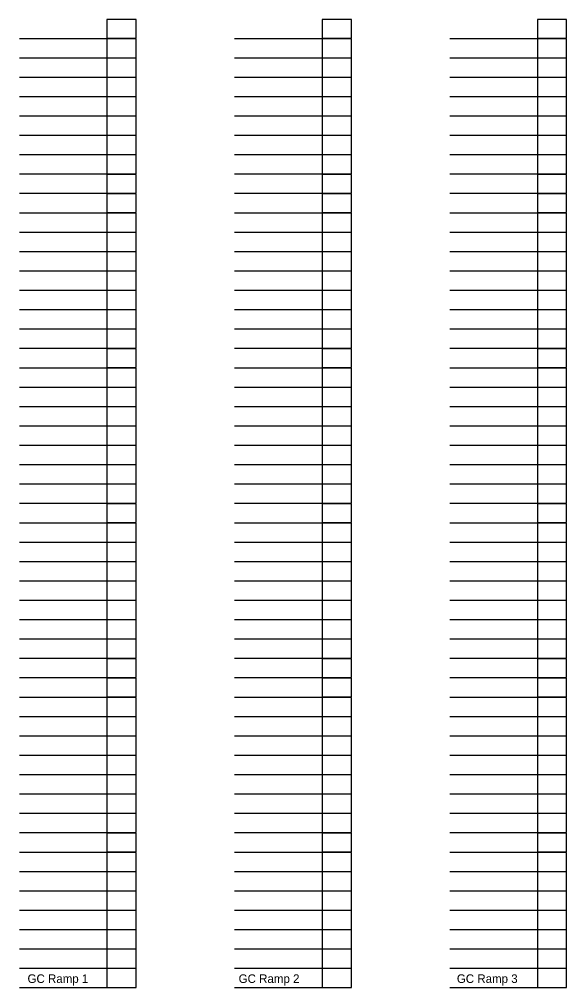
# Model space of a CAD drawing. Extents: x 625451 to 4181825, y 337941 to 441164.
# Drawn here: x 689151 to 701862, y 373673 to 396164 of the extents above; entities that cross this region are included whole.
import ezdxf

# ---------------------------------------------------------------- set-up
doc = ezdxf.new("R2010")
doc.units = 0
for name, color, linetype in [('PLOT_BDR-NOTUSED', 7, 'Continuous'), ('R_CX_Layout-GCRamp1', 7, 'Continuous'), ('R_CX_Layout-GCRamp2', 7, 'Continuous'), ('R_CX_Layout-GCRamp3', 7, 'Continuous'), ('R_No Plot_SEG2_FR', 7, 'Continuous')]:
    doc.layers.add(name, color=color, linetype=linetype)

msp = doc.modelspace()

# ---------------------------------------------------------------- linework, layer by layer
at = {"layer": 'PLOT_BDR-NOTUSED'}
for points in [[(691863, 396164), (691183, 396164), (691183, 395724), (691863, 395724)], [(696863, 396164), (696183, 396164), (696183, 395724), (696863, 395724)], [(701862, 396164), (701182, 396164), (701182, 395724), (701862, 395724)], [(691863, 395714), (691183, 395714), (691183, 395274), (691863, 395274)], [(696863, 395714), (696183, 395714), (696183, 395274), (696863, 395274)], [(701862, 395714), (701182, 395714), (701182, 395274), (701862, 395274)], [(691863, 395264), (691183, 395264), (691183, 394824), (691863, 394824)], [(696863, 395264), (696183, 395264), (696183, 394824), (696863, 394824)], [(701862, 395264), (701182, 395264), (701182, 394824), (701862, 394824)], [(691863, 394814), (691183, 394814), (691183, 394374), (691863, 394374)], [(696863, 394814), (696183, 394814), (696183, 394374), (696863, 394374)], [(701862, 394814), (701182, 394814), (701182, 394374), (701862, 394374)], [(691863, 394364), (691183, 394364), (691183, 393924), (691863, 393924)], [(696863, 394364), (696183, 394364), (696183, 393924), (696863, 393924)], [(701862, 394364), (701182, 394364), (701182, 393924), (701862, 393924)], [(691863, 393914), (691183, 393914), (691183, 393474), (691863, 393474)], [(696863, 393914), (696183, 393914), (696183, 393474), (696863, 393474)], [(701862, 393914), (701182, 393914), (701182, 393474), (701862, 393474)], [(691863, 393464), (691183, 393464), (691183, 393024), (691863, 393024)], [(696863, 393464), (696183, 393464), (696183, 393024), (696863, 393024)], [(701862, 393464), (701182, 393464), (701182, 393024), (701862, 393024)], [(691863, 393014), (691183, 393014), (691183, 392574), (691863, 392574)], [(696863, 393014), (696183, 393014), (696183, 392574), (696863, 392574)], [(701862, 393014), (701182, 393014), (701182, 392574), (701862, 392574)], [(691863, 392564), (691183, 392564), (691183, 392124), (691863, 392124)], [(696863, 392564), (696183, 392564), (696183, 392124), (696863, 392124)], [(701862, 392564), (701182, 392564), (701182, 392124), (701862, 392124)], [(691863, 392114), (691183, 392114), (691183, 391674), (691863, 391674)], [(696863, 392114), (696183, 392114), (696183, 391674), (696863, 391674)], [(701862, 392114), (701182, 392114), (701182, 391674), (701862, 391674)], [(691863, 391664), (691183, 391664), (691183, 391224), (691863, 391224)], [(696863, 391664), (696183, 391664), (696183, 391224), (696863, 391224)], [(701862, 391664), (701182, 391664), (701182, 391224), (701862, 391224)], [(691863, 391214), (691183, 391214), (691183, 390774), (691863, 390774)], [(696863, 391214), (696183, 391214), (696183, 390774), (696863, 390774)], [(701862, 391214), (701182, 391214), (701182, 390774), (701862, 390774)], [(691863, 390764), (691183, 390764), (691183, 390324), (691863, 390324)], [(696863, 390764), (696183, 390764), (696183, 390324), (696863, 390324)], [(701862, 390764), (701182, 390764), (701182, 390324), (701862, 390324)], [(691863, 390314), (691183, 390314), (691183, 389874), (691863, 389874)], [(696863, 390314), (696183, 390314), (696183, 389874), (696863, 389874)], [(701862, 390314), (701182, 390314), (701182, 389874), (701862, 389874)], [(691863, 389864), (691183, 389864), (691183, 389424), (691863, 389424)], [(696863, 389864), (696183, 389864), (696183, 389424), (696863, 389424)], [(701862, 389864), (701182, 389864), (701182, 389424), (701862, 389424)], [(691863, 389414), (691183, 389414), (691183, 388974), (691863, 388974)], [(696863, 389414), (696183, 389414), (696183, 388974), (696863, 388974)], [(701862, 389414), (701182, 389414), (701182, 388974), (701862, 388974)], [(691863, 388964), (691183, 388964), (691183, 388524), (691863, 388524)], [(696863, 388964), (696183, 388964), (696183, 388524), (696863, 388524)], [(701862, 388964), (701182, 388964), (701182, 388524), (701862, 388524)], [(691863, 388514), (691183, 388514), (691183, 388074), (691863, 388074)], [(696863, 388514), (696183, 388514), (696183, 388074), (696863, 388074)], [(701862, 388514), (701182, 388514), (701182, 388074), (701862, 388074)], [(691863, 388064), (691183, 388064), (691183, 387624), (691863, 387624)], [(696863, 388064), (696183, 388064), (696183, 387624), (696863, 387624)], [(701862, 388064), (701182, 388064), (701182, 387624), (701862, 387624)], [(691863, 387614), (691183, 387614), (691183, 387174), (691863, 387174)], [(696863, 387614), (696183, 387614), (696183, 387174), (696863, 387174)], [(701862, 387614), (701182, 387614), (701182, 387174), (701862, 387174)], [(691863, 387164), (691183, 387164), (691183, 386724), (691863, 386724)], [(696863, 387164), (696183, 387164), (696183, 386724), (696863, 386724)], [(701862, 387164), (701182, 387164), (701182, 386724), (701862, 386724)], [(691863, 386714), (691183, 386714), (691183, 386274), (691863, 386274)], [(696863, 386714), (696183, 386714), (696183, 386274), (696863, 386274)], [(701862, 386714), (701182, 386714), (701182, 386274), (701862, 386274)], [(691863, 386264), (691183, 386264), (691183, 385824), (691863, 385824)], [(696863, 386264), (696183, 386264), (696183, 385824), (696863, 385824)], [(701862, 386264), (701182, 386264), (701182, 385824), (701862, 385824)], [(691863, 385814), (691183, 385814), (691183, 385374), (691863, 385374)], [(696863, 385814), (696183, 385814), (696183, 385374), (696863, 385374)], [(701862, 385814), (701182, 385814), (701182, 385374), (701862, 385374)], [(691863, 385364), (691183, 385364), (691183, 384924), (691863, 384924)], [(696863, 385364), (696183, 385364), (696183, 384924), (696863, 384924)], [(701862, 385364), (701182, 385364), (701182, 384924), (701862, 384924)], [(691863, 384914), (691183, 384914), (691183, 384474), (691863, 384474)], [(696863, 384914), (696183, 384914), (696183, 384474), (696863, 384474)], [(701862, 384914), (701182, 384914), (701182, 384474), (701862, 384474)], [(691863, 384464), (691183, 384464), (691183, 384024), (691863, 384024)], [(696863, 384464), (696183, 384464), (696183, 384024), (696863, 384024)], [(701862, 384464), (701182, 384464), (701182, 384024), (701862, 384024)], [(691863, 384014), (691183, 384014), (691183, 383574), (691863, 383574)], [(696863, 384014), (696183, 384014), (696183, 383574), (696863, 383574)], [(701862, 384014), (701182, 384014), (701182, 383574), (701862, 383574)], [(691863, 383564), (691183, 383564), (691183, 383124), (691863, 383124)], [(696863, 383564), (696183, 383564), (696183, 383124), (696863, 383124)], [(701862, 383564), (701182, 383564), (701182, 383124), (701862, 383124)], [(691863, 383114), (691183, 383114), (691183, 382674), (691863, 382674)], [(696863, 383114), (696183, 383114), (696183, 382674), (696863, 382674)], [(701862, 383114), (701182, 383114), (701182, 382674), (701862, 382674)], [(691863, 382664), (691183, 382664), (691183, 382224), (691863, 382224)], [(696863, 382664), (696183, 382664), (696183, 382224), (696863, 382224)], [(701862, 382664), (701182, 382664), (701182, 382224), (701862, 382224)], [(691863, 382214), (691183, 382214), (691183, 381774), (691863, 381774)], [(696863, 382214), (696183, 382214), (696183, 381774), (696863, 381774)], [(701862, 382214), (701182, 382214), (701182, 381774), (701862, 381774)], [(691863, 381764), (691183, 381764), (691183, 381324), (691863, 381324)], [(696863, 381764), (696183, 381764), (696183, 381324), (696863, 381324)], [(701862, 381764), (701182, 381764), (701182, 381324), (701862, 381324)], [(691863, 381314), (691183, 381314), (691183, 380874), (691863, 380874)], [(696863, 381314), (696183, 381314), (696183, 380874), (696863, 380874)], [(701862, 381314), (701182, 381314), (701182, 380874), (701862, 380874)], [(691863, 380864), (691183, 380864), (691183, 380424), (691863, 380424)], [(696863, 380864), (696183, 380864), (696183, 380424), (696863, 380424)], [(701862, 380864), (701182, 380864), (701182, 380424), (701862, 380424)], [(691863, 380414), (691183, 380414), (691183, 379974), (691863, 379974)], [(696863, 380414), (696183, 380414), (696183, 379974), (696863, 379974)], [(701862, 380414), (701182, 380414), (701182, 379974), (701862, 379974)], [(691863, 379964), (691183, 379964), (691183, 379524), (691863, 379524)], [(696863, 379964), (696183, 379964), (696183, 379524), (696863, 379524)], [(701862, 379964), (701182, 379964), (701182, 379524), (701862, 379524)], [(691863, 379514), (691183, 379514), (691183, 379074), (691863, 379074)], [(696863, 379514), (696183, 379514), (696183, 379074), (696863, 379074)], [(701862, 379514), (701182, 379514), (701182, 379074), (701862, 379074)], [(691863, 379064), (691183, 379064), (691183, 378624), (691863, 378624)], [(696863, 379064), (696183, 379064), (696183, 378624), (696863, 378624)], [(701862, 379064), (701182, 379064), (701182, 378624), (701862, 378624)], [(691863, 378614), (691183, 378614), (691183, 378174), (691863, 378174)], [(696863, 378614), (696183, 378614), (696183, 378174), (696863, 378174)], [(701862, 378614), (701182, 378614), (701182, 378174), (701862, 378174)], [(691863, 378164), (691183, 378164), (691183, 377724), (691863, 377724)], [(696863, 378164), (696183, 378164), (696183, 377724), (696863, 377724)], [(701862, 378164), (701182, 378164), (701182, 377724), (701862, 377724)], [(691863, 377714), (691183, 377714), (691183, 377274), (691863, 377274)], [(696863, 377714), (696183, 377714), (696183, 377274), (696863, 377274)], [(701862, 377714), (701182, 377714), (701182, 377274), (701862, 377274)], [(691863, 377264), (691183, 377264), (691183, 376824), (691863, 376824)], [(696863, 377264), (696183, 377264), (696183, 376824), (696863, 376824)], [(701862, 377264), (701182, 377264), (701182, 376824), (701862, 376824)], [(691863, 376814), (691183, 376814), (691183, 376374), (691863, 376374)], [(696863, 376814), (696183, 376814), (696183, 376374), (696863, 376374)], [(701862, 376814), (701182, 376814), (701182, 376374), (701862, 376374)], [(696863, 376364), (696183, 376364), (696183, 375924), (696863, 375924)], [(701862, 376364), (701182, 376364), (701182, 375924), (701862, 375924)], [(701862, 375914), (701182, 375914), (701182, 375474), (701862, 375474)], [(701862, 375464), (701182, 375464), (701182, 375024), (701862, 375024)]]:
    msp.add_lwpolyline(points, close=True, dxfattribs=at)
at = {"layer": 'R_CX_Layout-GCRamp1'}
for p, q in [((689151, 395723), (691250, 395723)), ((689152, 395723), (691251, 395723)), ((689151, 395273), (691250, 395273)), ((689152, 395273), (691251, 395273)), ((689151, 394823), (691250, 394823)), ((689152, 394823), (691251, 394823)), ((689151, 394373), (691250, 394373)), ((689152, 394373), (691251, 394373)), ((689151, 393923), (691250, 393923)), ((689152, 393923), (691251, 393923)), ((689151, 393473), (691250, 393473)), ((689152, 393473), (691251, 393473)), ((689151, 393023), (691250, 393023)), ((689152, 393023), (691251, 393023)), ((689151, 392573), (691250, 392573)), ((689152, 392573), (691251, 392573)), ((689151, 392123), (691250, 392123)), ((689152, 392123), (691251, 392123)), ((689151, 391673), (691250, 391673)), ((689152, 391673), (691251, 391673)), ((689151, 391223), (691250, 391223)), ((689152, 391223), (691251, 391223)), ((689151, 390773), (691250, 390773)), ((689152, 390773), (691251, 390773)), ((689151, 390323), (691250, 390323)), ((689152, 390323), (691251, 390323)), ((689151, 389873), (691250, 389873)), ((689152, 389873), (691251, 389873)), ((689151, 389423), (691250, 389423)), ((689152, 389423), (691251, 389423)), ((689151, 388973), (691250, 388973)), ((689152, 388973), (691251, 388973)), ((689151, 388523), (691250, 388523)), ((689152, 388523), (691251, 388523)), ((689151, 388073), (691250, 388073)), ((689152, 388073), (691251, 388073)), ((689151, 387623), (691250, 387623)), ((689152, 387623), (691251, 387623)), ((689151, 387173), (691250, 387173)), ((689152, 387173), (691251, 387173)), ((689151, 386723), (691250, 386723)), ((689152, 386723), (691251, 386723)), ((689151, 386273), (691250, 386273)), ((689152, 386273), (691251, 386273)), ((689151, 385823), (691250, 385823)), ((689152, 385823), (691251, 385823)), ((689151, 385373), (691250, 385373)), ((689152, 385373), (691251, 385373)), ((689151, 384923), (691250, 384923)), ((689152, 384923), (691251, 384923)), ((689151, 384473), (691250, 384473)), ((689152, 384473), (691251, 384473)), ((689151, 384023), (691250, 384023)), ((689152, 384023), (691251, 384023)), ((689151, 383573), (691250, 383573)), ((689152, 383573), (691251, 383573)), ((689151, 383123), (691250, 383123)), ((689152, 383123), (691251, 383123)), ((689151, 382673), (691250, 382673)), ((689152, 382673), (691251, 382673)), ((689151, 382223), (691250, 382223)), ((689152, 382223), (691251, 382223)), ((689151, 381773), (691250, 381773)), ((689152, 381773), (691251, 381773)), ((689151, 381323), (691250, 381323)), ((689152, 381323), (691251, 381323)), ((689151, 380873), (691250, 380873)), ((689152, 380873), (691251, 380873)), ((689151, 380423), (691250, 380423)), ((689152, 380423), (691251, 380423)), ((689151, 379973), (691250, 379973)), ((689152, 379973), (691251, 379973)), ((689151, 379523), (691250, 379523)), ((689152, 379523), (691251, 379523)), ((689151, 379073), (691250, 379073)), ((689152, 379073), (691251, 379073)), ((689151, 378623), (691250, 378623)), ((689152, 378623), (691251, 378623)), ((689151, 378173), (691250, 378173)), ((689152, 378173), (691251, 378173)), ((689151, 377723), (691250, 377723)), ((689152, 377723), (691251, 377723)), ((689151, 377273), (691250, 377273)), ((689152, 377273), (691251, 377273)), ((689151, 376823), (691250, 376823)), ((689152, 376823), (691251, 376823)), ((689151, 376373), (691250, 376373)), ((689152, 376373), (691251, 376373)), ((689151, 375923), (691250, 375923)), ((689152, 375923), (691251, 375923)), ((689151, 375473), (691250, 375473)), ((689152, 375473), (691251, 375473)), ((689151, 375023), (691250, 375023)), ((689152, 375023), (691251, 375023)), ((689151, 374573), (691250, 374573)), ((689152, 374573), (691251, 374573)), ((689151, 374123), (691250, 374123)), ((689152, 374123), (691251, 374123)), ((689151, 373673), (691250, 373673)), ((689152, 373673), (691251, 373673))]:
    msp.add_line(p, q, dxfattribs=at)
at = {"layer": 'R_CX_Layout-GCRamp2'}
for p, q in [((694151, 395723), (696250, 395723)), ((694152, 395723), (696251, 395723)), ((694151, 395273), (696250, 395273)), ((694152, 395273), (696251, 395273)), ((694151, 394823), (696250, 394823)), ((694152, 394823), (696251, 394823)), ((694151, 394373), (696250, 394373)), ((694152, 394373), (696251, 394373)), ((694151, 393923), (696250, 393923)), ((694152, 393923), (696251, 393923)), ((694151, 393473), (696250, 393473)), ((694152, 393473), (696251, 393473)), ((694151, 393023), (696250, 393023)), ((694152, 393023), (696251, 393023)), ((694151, 392573), (696250, 392573)), ((694152, 392573), (696251, 392573)), ((694151, 392123), (696250, 392123)), ((694152, 392123), (696251, 392123)), ((694151, 391673), (696250, 391673)), ((694152, 391673), (696251, 391673)), ((694151, 391223), (696250, 391223)), ((694152, 391223), (696251, 391223)), ((694151, 390773), (696250, 390773)), ((694152, 390773), (696251, 390773)), ((694151, 390323), (696250, 390323)), ((694152, 390323), (696251, 390323)), ((694151, 389873), (696250, 389873)), ((694152, 389873), (696251, 389873)), ((694151, 389423), (696250, 389423)), ((694152, 389423), (696251, 389423)), ((694151, 388973), (696250, 388973)), ((694152, 388973), (696251, 388973)), ((694151, 388523), (696250, 388523)), ((694152, 388523), (696251, 388523)), ((694151, 388073), (696250, 388073)), ((694152, 388073), (696251, 388073)), ((694151, 387623), (696250, 387623)), ((694152, 387623), (696251, 387623)), ((694151, 387173), (696250, 387173)), ((694152, 387173), (696251, 387173)), ((694151, 386723), (696250, 386723)), ((694152, 386723), (696251, 386723)), ((694151, 386273), (696250, 386273)), ((694152, 386273), (696251, 386273)), ((694151, 385823), (696250, 385823)), ((694152, 385823), (696251, 385823)), ((694151, 385373), (696250, 385373)), ((694152, 385373), (696251, 385373)), ((694151, 384923), (696250, 384923)), ((694152, 384923), (696251, 384923)), ((694151, 384473), (696250, 384473)), ((694152, 384473), (696251, 384473)), ((694151, 384023), (696250, 384023)), ((694152, 384023), (696251, 384023)), ((694151, 383573), (696250, 383573)), ((694152, 383573), (696251, 383573)), ((694151, 383123), (696250, 383123)), ((694152, 383123), (696251, 383123)), ((694151, 382673), (696250, 382673)), ((694152, 382673), (696251, 382673)), ((694151, 382223), (696250, 382223)), ((694152, 382223), (696251, 382223)), ((694151, 381773), (696250, 381773)), ((694152, 381773), (696251, 381773)), ((694151, 381323), (696250, 381323)), ((694152, 381323), (696251, 381323)), ((694151, 380873), (696250, 380873)), ((694152, 380873), (696251, 380873)), ((694151, 380423), (696250, 380423)), ((694152, 380423), (696251, 380423)), ((694151, 379973), (696250, 379973)), ((694152, 379973), (696251, 379973)), ((694151, 379523), (696250, 379523)), ((694152, 379523), (696251, 379523)), ((694151, 379073), (696250, 379073)), ((694152, 379073), (696251, 379073)), ((694151, 378623), (696250, 378623)), ((694152, 378623), (696251, 378623)), ((694151, 378173), (696250, 378173)), ((694152, 378173), (696251, 378173)), ((694151, 377723), (696250, 377723)), ((694152, 377723), (696251, 377723)), ((694151, 377273), (696250, 377273)), ((694152, 377273), (696251, 377273)), ((694151, 376823), (696250, 376823)), ((694152, 376823), (696251, 376823)), ((694151, 376373), (696250, 376373)), ((694152, 376373), (696251, 376373)), ((694151, 375923), (696250, 375923)), ((694152, 375923), (696251, 375923)), ((694151, 375473), (696250, 375473)), ((694152, 375473), (696251, 375473)), ((694151, 375023), (696250, 375023)), ((694152, 375023), (696251, 375023)), ((694151, 374573), (696250, 374573)), ((694152, 374573), (696251, 374573)), ((694151, 374123), (696250, 374123)), ((694152, 374123), (696251, 374123)), ((694151, 373673), (696250, 373673)), ((694152, 373673), (696251, 373673))]:
    msp.add_line(p, q, dxfattribs=at)
at = {"layer": 'R_CX_Layout-GCRamp3'}
for p, q in [((699151, 395723), (701250, 395723)), ((699151, 395273), (701250, 395273)), ((699151, 394823), (701250, 394823)), ((699151, 394373), (701250, 394373)), ((699151, 393923), (701250, 393923)), ((699151, 393473), (701250, 393473)), ((699151, 393023), (701250, 393023)), ((699151, 392573), (701250, 392573)), ((699151, 392123), (701250, 392123)), ((699151, 391673), (701250, 391673)), ((699151, 391223), (701250, 391223)), ((699151, 390773), (701250, 390773)), ((699151, 390323), (701250, 390323)), ((699151, 389873), (701250, 389873)), ((699151, 389423), (701250, 389423)), ((699151, 388973), (701250, 388973)), ((699151, 388523), (701250, 388523)), ((699151, 388073), (701250, 388073)), ((699151, 387623), (701250, 387623)), ((699151, 387173), (701250, 387173)), ((699151, 386723), (701250, 386723)), ((699151, 386273), (701250, 386273)), ((699151, 385823), (701250, 385823)), ((699151, 385373), (701250, 385373)), ((699151, 384923), (701250, 384923)), ((699151, 384473), (701250, 384473)), ((699151, 384023), (701250, 384023)), ((699151, 383573), (701250, 383573)), ((699151, 383123), (701250, 383123)), ((699151, 382673), (701250, 382673)), ((699151, 382223), (701250, 382223)), ((699151, 381773), (701250, 381773)), ((699151, 381323), (701250, 381323)), ((699151, 380873), (701250, 380873)), ((699151, 380423), (701250, 380423)), ((699151, 379973), (701250, 379973)), ((699151, 379523), (701250, 379523)), ((699151, 379073), (701250, 379073)), ((699151, 378623), (701250, 378623)), ((699151, 378173), (701250, 378173)), ((699151, 377723), (701250, 377723)), ((699151, 377273), (701250, 377273)), ((699151, 376823), (701250, 376823)), ((699151, 376373), (701250, 376373)), ((699151, 375923), (701250, 375923)), ((699151, 375473), (701250, 375473)), ((699151, 375023), (701250, 375023)), ((699151, 374573), (701250, 374573)), ((699151, 374123), (701250, 374123)), ((699151, 373673), (701250, 373673))]:
    msp.add_line(p, q, dxfattribs=at)
at = {"layer": 'R_No Plot_SEG2_FR'}
for points in [[(691863, 376364), (691183, 376364), (691183, 375924), (691863, 375924)], [(691863, 375914), (691183, 375914), (691183, 375474), (691863, 375474)], [(696863, 375914), (696183, 375914), (696183, 375474), (696863, 375474)], [(691863, 375464), (691183, 375464), (691183, 375024), (691863, 375024)], [(696863, 375464), (696183, 375464), (696183, 375024), (696863, 375024)], [(691863, 375014), (691183, 375014), (691183, 374574), (691863, 374574)], [(696863, 375014), (696183, 375014), (696183, 374574), (696863, 374574)], [(701862, 375014), (701182, 375014), (701182, 374574), (701862, 374574)], [(691863, 374564), (691183, 374564), (691183, 374124), (691863, 374124)], [(696863, 374564), (696183, 374564), (696183, 374124), (696863, 374124)], [(701862, 374564), (701182, 374564), (701182, 374124), (701862, 374124)], [(691863, 374114), (691183, 374114), (691183, 373674), (691863, 373674)], [(696863, 374114), (696183, 374114), (696183, 373674), (696863, 373674)], [(701862, 374114), (701182, 374114), (701182, 373674), (701862, 373674)]]:
    msp.add_lwpolyline(points, close=True, dxfattribs=at)

# ---------------------------------------------------------------- texts
at = {"layer": 'R_CX_Layout-GCRamp1'}
msp.add_text('GC Ramp 1', height=200, dxfattribs=at).set_placement((689340, 373781))
at = {"layer": 'R_CX_Layout-GCRamp2'}
msp.add_text('GC Ramp 2', height=200, dxfattribs=at).set_placement((694244, 373781))
at = {"layer": 'R_CX_Layout-GCRamp3'}
msp.add_text('GC Ramp 3', height=200, dxfattribs=at).set_placement((699312, 373781))

doc.saveas('drawing.dxf')
